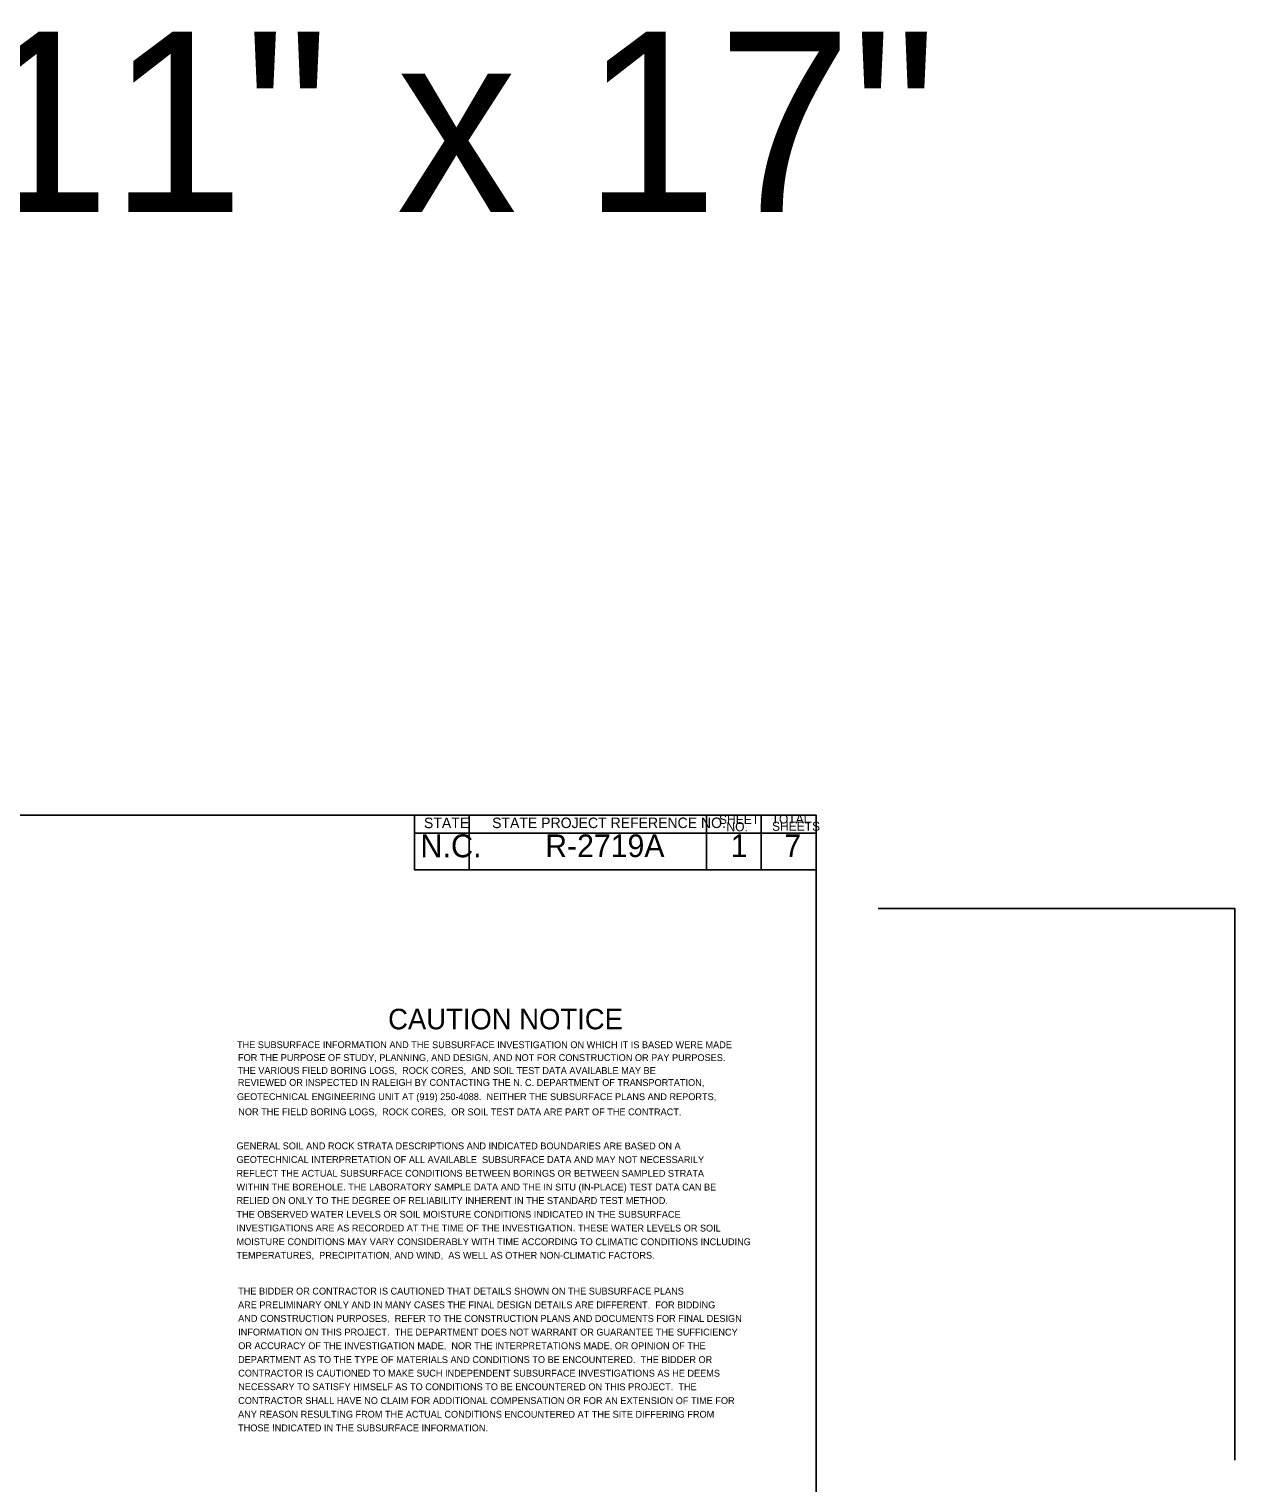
# Model space of a CAD drawing. Extents: x 278710 to 279187, y 171464 to 171625.
# Drawn here: x 278863.6 to 278930.6, y 171543.9 to 171624.6 of the extents above; entities that cross this region are included whole.
import ezdxf

# ---------------------------------------------------------------- set-up
doc = ezdxf.new("R2010")
doc.units = 0
doc.layers.add('Geotech Sheets and Borders Cell', color=7, linetype='Continuous')
doc.layers.add('Prop Strc Sect_ Misc - User Comment (Tx - small)', color=7, linetype='Continuous')

msp = doc.modelspace()

# ---------------------------------------------------------------- linework, layer by layer
at = {"layer": 'Geotech Sheets and Borders Cell'}
for p, q in [((278907.688, 171581.254), (278907.688, 171581.254)), ((278888.076, 171580.949), (278888.076, 171577.914)), ((278901.255, 171580.949), (278901.255, 171577.914)), ((278904.296, 171580.949), (278904.296, 171577.914)), ((278885.034, 171579.94), (278907.338, 171579.94))]:
    msp.add_line(p, q, dxfattribs=at)
for points in [[(278756.087, 171580.949), (278907.338, 171580.949), (278907.338, 171476.081), (278756.087, 171476.081)], [(278885.034, 171580.949), (278907.338, 171580.949), (278907.338, 171577.914), (278885.034, 171577.914)]]:
    msp.add_lwpolyline(points, close=True, dxfattribs=at)
msp.add_lwpolyline([(278930.598, 171545.139), (278930.598, 171575.763), (278910.782, 171575.763)], dxfattribs=at)

# ---------------------------------------------------------------- texts
for s, height, rotation, p in [('SHEET', 0.4992, 0.01521, (278901.951, 171580.455)), ('TOTAL', 0.4992, 0.01521, (278904.871, 171580.484)), ('STATE', 0.5824, 0.01521, (278885.566, 171580.226)), ('STATE PROJECT REFERENCE NO.', 0.5824, 0.01521, (278889.352, 171580.227)), ('NO.', 0.4992, 0.01521, (278902.364, 171580.053)), ('SHEETS', 0.4992, 0.01521, (278904.891, 171580.078)), ('N.C.', 1.2711, 0.01521, (278885.368, 171578.607)), ('R-2719A', 1.2552, 0.01521, (278892.299, 171578.618)), ('1', 1.255, 0.01521, (278902.595, 171578.619)), ('7', 1.255, 0.01521, (278905.575, 171578.619)), ('CAUTION NOTICE ', 1.13956, 359.99161, (278883.576, 171569.056)), ('THE SUBSURFACE INFORMATION AND THE SUBSURFACE INVESTIGATION ON WHICH IT IS BASED WERE MADE', 0.3798, 359.99161, (278875.183, 171568.012)), ('FOR THE PURPOSE OF STUDY, PLANNING, AND DESIGN, AND NOT FOR CONSTRUCTION OR PAY PURPOSES. ', 0.3798, 359.99161, (278875.242, 171567.298)), ('THE VARIOUS FIELD BORING LOGS,  ROCK CORES,  AND SOIL TEST DATA AVAILABLE MAY BE ', 0.3798, 359.99161, (278875.211, 171566.582)), ('REVIEWED OR INSPECTED IN RALEIGH BY CONTACTING THE N. C. DEPARTMENT OF TRANSPORTATION, ', 0.3798, 359.99161, (278875.231, 171565.916)), ('GEOTECHNICAL ENGINEERING UNIT AT (919) 250-4088.  NEITHER THE SUBSURFACE PLANS AND REPORTS,', 0.3798, 359.99161, (278875.181, 171565.128)), ('NOR THE FIELD BORING LOGS,  ROCK CORES,  OR SOIL TEST DATA ARE PART OF THE CONTRACT.', 0.3798, 359.99161, (278875.256, 171564.287)), ('GENERAL SOIL AND ROCK STRATA DESCRIPTIONS AND INDICATED BOUNDARIES ARE BASED ON A', 0.3798, 359.99161, (278875.154, 171562.396)), ('GEOTECHNICAL INTERPRETATION OF ALL AVAILABLE  SUBSURFACE DATA AND MAY NOT NECESSARILY', 0.3798, 359.99161, (278875.159, 171561.637)), ('REFLECT THE ACTUAL SUBSURFACE CONDITIONS BETWEEN BORINGS OR BETWEEN SAMPLED STRATA ', 0.3798, 359.99161, (278875.155, 171560.874)), ('WITHIN THE BOREHOLE. THE LABORATORY SAMPLE DATA AND THE IN SITU (IN-PLACE) TEST DATA CAN BE', 0.3798, 359.99161, (278875.155, 171560.111)), ('RELIED ON ONLY TO THE DEGREE OF RELIABILITY INHERENT IN THE STANDARD TEST METHOD.', 0.3798, 359.99161, (278875.155, 171559.362)), ('THE OBSERVED WATER LEVELS OR SOIL MOISTURE CONDITIONS INDICATED IN THE SUBSURFACE ', 0.3798, 359.99161, (278875.155, 171558.599)), ('INVESTIGATIONS ARE AS RECORDED AT THE TIME OF THE INVESTIGATION. THESE WATER LEVELS OR SOIL', 0.3798, 359.99161, (278875.155, 171557.835)), ('MOISTURE CONDITIONS MAY VARY CONSIDERABLY WITH TIME ACCORDING TO CLIMATIC CONDITIONS INCLUDING', 0.3798, 359.99161, (278875.16, 171557.076)), ('TEMPERATURES,  PRECIPITATION, AND WIND,  AS WELL AS OTHER NON-CLIMATIC FACTORS.', 0.3798, 359.99161, (278875.15, 171556.323)), ('THE BIDDER OR CONTRACTOR IS CAUTIONED THAT DETAILS SHOWN ON THE SUBSURFACE PLANS', 0.3798, 359.99161, (278875.249, 171554.334)), ('ARE PRELIMINARY ONLY AND IN MANY CASES THE FINAL DESIGN DETAILS ARE DIFFERENT.  FOR BIDDING', 0.3798, 359.99161, (278875.244, 171553.571)), ('AND CONSTRUCTION PURPOSES,  REFER TO THE CONSTRUCTION PLANS AND DOCUMENTS FOR FINAL DESIGN', 0.3798, 359.99161, (278875.249, 171552.817)), ('INFORMATION ON THIS PROJECT.  THE DEPARTMENT DOES NOT WARRANT OR GUARANTEE THE SUFFICIENCY', 0.3798, 359.99161, (278875.249, 171552.059)), ('OR ACCURACY OF THE INVESTIGATION MADE,  NOR THE INTERPRETATIONS MADE, OR OPINION OF THE ', 0.37927, 359.99161, (278875.254, 171551.3)), ('DEPARTMENT AS TO THE TYPE OF MATERIALS AND CONDITIONS TO BE ENCOUNTERED.  THE BIDDER OR', 0.3798, 359.99161, (278875.245, 171550.532)), ('CONTRACTOR IS CAUTIONED TO MAKE SUCH INDEPENDENT SUBSURFACE INVESTIGATIONS AS HE DEEMS', 0.3798, 359.99161, (278875.25, 171549.778)), ('NECESSARY TO SATISFY HIMSELF AS TO CONDITIONS TO BE ENCOUNTERED ON THIS PROJECT.  THE', 0.3798, 359.99161, (278875.255, 171549.024)), ('ANY REASON RESULTING FROM THE ACTUAL CONDITIONS ENCOUNTERED AT THE SITE DIFFERING FROM ', 0.3798, 359.99161, (278875.246, 171547.498)), ('CONTRACTOR SHALL HAVE NO CLAIM FOR ADDITIONAL COMPENSATION OR FOR AN EXTENSION OF TIME FOR', 0.3798, 359.99161, (278875.25, 171548.256)), ('THOSE INDICATED IN THE SUBSURFACE INFORMATION.', 0.37965, 359.99161, (278875.246, 171546.739))]:
    msp.add_text(s, height=height, rotation=rotation, dxfattribs=at).set_placement(p)
at = {"layer": 'Prop Strc Sect_ Misc - User Comment (Tx - small)'}
msp.add_text('TITLE SHEET: 11" x 17"', height=10, dxfattribs=at).set_placement((278768.566, 171614.437))

doc.saveas('drawing.dxf')
